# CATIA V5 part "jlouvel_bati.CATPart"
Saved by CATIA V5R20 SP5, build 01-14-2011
Part number: bati
Bounding box of the stored display mesh (mm): x -10 to 32, y -80 to 20, z -340.45 to 309.55
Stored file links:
  E:\IAO_2010\iao\IAO_MMS_Groupe2\IAO_MMS_Groupe2\OK\jlouvel\jlouvel_iao\pièces cao catia ifma\jlouvel_bati.CATPart
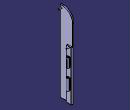
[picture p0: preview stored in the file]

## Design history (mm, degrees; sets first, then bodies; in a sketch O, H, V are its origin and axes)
Body1 (main body)
  Sketch1 on yz-plane, origin (0, 0, 0), H (0, 1, 0), V (0, 0, 1)
    line L1 (-20, 59.5496) -> (20, 59.5496)
    line L2 (20, 59.5496) -> (20, -340.4504)
    line L3 (20, -340.4504) -> (-20, -340.4504)
    line L4 (-20, -340.4504) -> (-20, 59.5496)
    length L1 = 40
    length L2 = 400
    horizontal: L1 H, L3 H
    vertical: L2 V, L4 V
    symmetry: L2 L4 V
  Pad1: profile Sketch1, direction (1, 0, 0), length 10
  Sketch2 on end face of Pad1, origin (10, 0, 0), H (0, 1, 0), V (0, 0, 1)
    circle A1 centre (0, 52.5496) radius 2
    point P1 (0, 52.5496)
    reference projected line E1 (20, 59.5496) -> (-20, 59.5496) from edge [face of Pad1 from Sketch1.L1 | end face of Pad1]
    radius A1 = 2
    distance E1 A1 = 5
    coincidence: P1 V
  Pad2: profile Sketch2, direction (1, 0, 0), length 22
  Plane1: type Offset, RefPlane xy-plane, Offset -10
  Sketch3 on Plane1, origin (0, 0, -10), H (1, 0, 0), V (0, 1, 0)
    line L1 (10, 10) -> (17, 10)
    arc A1 centre (17, 0) radius 10 from (17, 10) to (17, -10) cw
    point P3 (17, 0)
    line L2 (17, -10) -> (10, -10)
    line L3 (10, -10) -> (10, 10)
    reference projected line E1 (10, 20) -> (10, -20) from edge [face of Pad1 from Sketch1.L1 | end face of Pad1]
    distance L3 E1 = 0
    distance P3 L3 = 7
    length L3 = 20
    horizontal: L1 H
    tangency: A1 L1, L2 A1
    vertical: L3 V
    symmetry: L2 L1 H
  Pad3: profile Sketch3, direction (0, 0, -1), length 75
  Plane2: type Offset, RefPlane xy-plane, Offset -200
  Sketch4 on Plane2, origin (0, 0, -200), H (1, 0, 0), V (0, 1, 0)
    line L1 (10, 10) -> (17, 10)
    point P2 (17, 10)
    point P3 (17, 10)
    arc A1 centre (17, 0) radius 10 from (17, 10) to (17, -10) cw
    line L2 (17, -10) -> (10, -10)
    line L3 (10, -10) -> (10, 10)
    reference projected line E1 (10, 20) -> (10, -20) from edge [face of Pad1 from Sketch1.L1 | end face of Pad1]
    length L1 = 7
    length L2 = 7
    length L3 = 20
    horizontal: L1 H
    tangency: L2 A1
    vertical: L3 V
    coincidence: L3 E1, P2 P3
    symmetry: L1 L2 H
  Pad4: profile Sketch4, direction (0, 0, -1), length 45, mirrored extent
  Sketch5 on start face of Pad3, origin (0, 0, -10), H (1, 0, 0), V (0, 1, 0)
    circle A1 centre (17, 0) radius 5
    point P1 (17, 0)
    reference projected line E1 (10, 20) -> (10, -20) from edge [face of Pad1 from Sketch1.L1 | end face of Pad1]
    radius A1 = 5
    distance P1 E1 = 7
    coincidence: P1 H
  Pocket1: profile Sketch5, direction (0, 0, -1), up to end face of Pad4
  Sketch6 on end face of Pad1, origin (10, 0, 0), H (0, 1, 0), V (0, 0, 1)
    circle A1 centre (0, 52.5496) radius 5
    reference projected circle E1 centre (0, 52.5496) radius 2 from edge [face of Pad2 from Sketch2.A1 | end face of Pad2]
    radius A1 = 5
    concentricity: A1 E1
  Pad5: profile Sketch6, direction (1, 0, 0), length 17
  Sketch7 on start face of Pad1, origin (0, 0, 0), H (0, -1, 0), V (0, 0, 1)
    line L1 (-20, -340.4504) -> (80, -340.4504)
    line L2 (80, -340.4504) -> (80, 309.5496)
    line L3 (80, 309.5496) -> (63.8442, 309.5496)
    line L4 (-20, 225.7054) -> (-20, -340.4504)
    point P3 (80, 309.5496)
    point P4 (-20, 309.5496)
    reference projected line E1 (-20, -340.4504) -> (-20, 59.5496) from edge [start face of Pad1 | face of Pad1 from Sketch1.L2]
    reference projected line E2 (20, -340.4504) -> (-20, -340.4504) from edge [start face of Pad1 | face of Pad1 from Sketch1.L3]
    reference projected line E3 (-20, 59.5496) -> (20, 59.5496) from edge [start face of Pad1 | face of Pad1 from Sketch1.L1]
    arc A1 centre (63.8442, 225.7054) radius 83.8442 from (-20, 225.7054) to (63.8442, 309.5496) cw
    distance L3 E3 = 250
    distance P3 P4 = 100
    radius A1 = 83.8442
    horizontal: L1 H, L3 H
    vertical: L2 V, L4 V
    coincidence: E1 L4, L1 E2, L4 P4, L3 P4
    tangency: A1 L4, A1 L3
  Pad6: profile Sketch7, direction (-1, 0, 0), length 10
  Sketch8 on start face of Pad6, origin (0, 0, 0), H (0, 1, 0), V (0, 0, 1)
    circle A1 centre (-70, 289.5496) radius 2
    point P1 (-70, 289.5496)
    circle A2 centre (-70, 289.5496) radius 5
    point P2 (-70, 289.5496)
    reference projected line E1 (-80, 309.5496) -> (20, 309.5496) from edge [start face of Pad6 | face of Pad6 from Sketch7.L3]
    reference projected line E2 (-80, -340.4504) -> (-80, 134.5496) from edge [start face of Pad6 | face of Pad6 from Sketch7.L2]
    distance P2 E1 = 20
    distance P2 E2 = 10
    radius A1 = 2
    radius A2 = 5
    coincidence: P2 P1
  MultiPad1: profile Sketch8, domains (length 19.5; length 24.5)
  Sketch9 on end face of Pad3, origin (0, 0, -85), H (1, 0, 0), V (0, -1, 0)
    line L1 (20, 3) -> (30, 3)
    line L2 (30, 3) -> (30, -3)
    line L3 (30, -3) -> (20, -3)
    line L4 (20, -3) -> (20, 3)
    distance L1 L3 = 6
    distance L1 H = 3
    horizontal: L1 H, L3 H
    vertical: L2 V, L4 V
  Pocket2: profile Sketch9, direction (0, 0, 1), length 60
